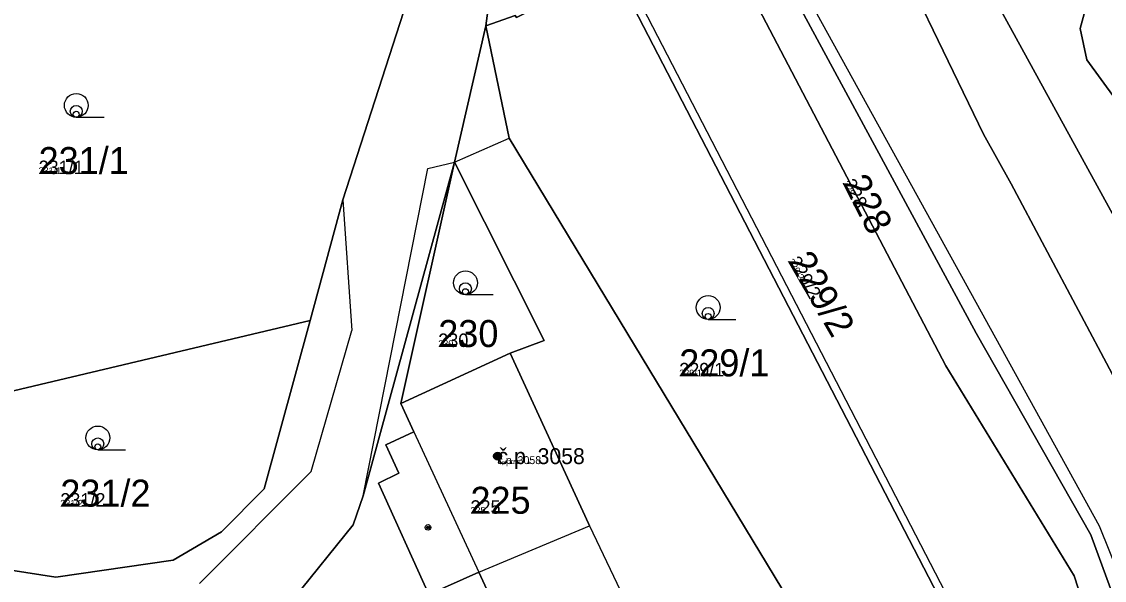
# Model space of a CAD drawing. Extents: x -759873 to -758487, y -975024 to -973516.
# Drawn here: x -759341.1 to -759272.8, y -974549.7 to -974514.5 of the extents above; entities that cross this region are included whole.
import ezdxf

# ---------------------------------------------------------------- set-up
doc = ezdxf.new("R2010")
doc.units = 0
for name, color, linetype in [('KAT_02_hranice parcel', 7, 'Continuous'), ('KAT_03_1000_st čísla parcelní', 7, 'Continuous'), ('KAT_03_1000_čísla parcelní', 7, 'Continuous'), ('KAT_03_1000_čísla popisná', 7, 'Continuous'), ('KAT_03_250_st čísla parcelní', 7, 'Continuous'), ('KAT_03_250_čísla parcelní', 7, 'Continuous'), ('KAT_03_250_čísla popisná', 7, 'Continuous'), ('KAT_03_500_st čísla parcelní', 7, 'Continuous'), ('KAT_03_500_čísla parcelní', 7, 'Continuous'), ('KAT_03_500_čísla popisná', 7, 'Continuous'), ('KAT_04_vnitřní kresba', 7, 'Continuous'), ('KAT_05_1000_značky kultur', 7, 'Continuous'), ('KAT_05_250_značky kultur', 7, 'Continuous'), ('KAT_05_500_značky kultur', 7, 'Continuous'), ('KAT_07_1000_značky budov', 7, 'Continuous'), ('KAT_07_250_značky budov', 7, 'Continuous'), ('KAT_07_500_značky budov', 7, 'Continuous'), ('KAT_14_plocha_budovy', 7, 'Continuous'), ('KAT_14_plocha_pozemek', 7, 'Continuous')]:
    doc.layers.add(name, color=color, linetype=linetype)

msp = doc.modelspace()

# ---------------------------------------------------------------- linework, layer by layer
at = {"layer": 'KAT_02_hranice parcel'}
for p, q in [((-759313.84, -974523.31), (-759311.87, -974514.72)), ((-759317.23, -974538.53), (-759313.84, -974523.31)), ((-759348.95, -974539.45), (-759322.95, -974533.3))]:
    msp.add_line(p, q, dxfattribs=at)
for points in [[(-759219.91, -974557.23), (-759223.23, -974544.52), (-759227.46, -974511.48), (-759228.38, -974500), (-759228.8, -974494.72), (-759282.45, -974508.14), (-759262.36, -974544.72), (-759253.18, -974586.18)], [(-759311.87, -974514.72), (-759311.45, -974511.72), (-759310.87, -974510.87), (-759307.53, -974503.56)], [(-759258.04, -974584.15), (-759260.14, -974570.39), (-759263.44, -974559.14), (-759268.52, -974545.49), (-759272.2, -974537), (-759272.35, -974536.66), (-759278.72, -974524.68), (-759280.47, -974521.55), (-759287.48, -974507.08)], [(-759296.72, -974509.67), (-759294.73, -974508.6), (-759280.94, -974534.1), (-759273.69, -974546.8), (-759272.46, -974550.18)], [(-759296.72, -974509.67), (-759282.85, -974536.15), (-759274.75, -974549.39), (-759274.26, -974550.88)], [(-759256.77, -974540.42), (-759273.95, -974516.88), (-759274.37, -974514.9), (-759273.84, -974512.95), (-759271.16, -974509.41)], [(-759303.45, -974511.79), (-759308.95, -974513.71), (-759309.93, -974514.21), (-759310.02, -974514.07), (-759311.87, -974514.72)], [(-759283.48, -974554.45), (-759282.94, -974552.16), (-759283.02, -974551.25), (-759303.45, -974511.79)], [(-759316.83, -974513.15), (-759320.88, -974525.7), (-759322.95, -974533.3)], [(-759293.18, -974550.19), (-759310.39, -974521.81), (-759311.87, -974514.72)], [(-759357.85, -974552.36), (-759338.42, -974554.93), (-759330.76, -974554.41), (-759323.99, -974550.85), (-759320.23, -974546.18), (-759319.6, -974544.34), (-759313.84, -974523.31)], [(-759313.84, -974523.31), (-759308.18, -974534.55), (-759310.32, -974535.35), (-759317.23, -974538.53)], [(-759322.95, -974533.3), (-759325.85, -974543.91), (-759328.53, -974546.61), (-759331.59, -974548.41), (-759338.98, -974549.47), (-759346.97, -974548.23)], [(-759304.47, -974566.09), (-759309.3, -974555.67), (-759312.31, -974549.16), (-759315.45, -974550.56), (-759318.62, -974543.56), (-759317.34, -974542.93), (-759318.17, -974541.13), (-759316.41, -974540.31), (-759317.23, -974538.53)]]:
    msp.add_lwpolyline(points, dxfattribs=at)
at = {"layer": 'KAT_03_1000_čísla popisná'}
msp.add_circle((-759311.12, -974541.85), 0.25, dxfattribs=at)
at = {"layer": 'KAT_03_250_čísla popisná'}
msp.add_circle((-759311.12, -974541.85), 0.0625, dxfattribs=at)
at = {"layer": 'KAT_03_500_čísla popisná'}
msp.add_circle((-759311.12, -974541.85), 0.125, dxfattribs=at)
at = {"layer": 'KAT_04_vnitřní kresba'}
for p, q in [((-759293.89, -974508.69), (-759273.17, -974546.25)), ((-759303.01, -974511.56), (-759282.58, -974551.02)), ((-759313.84, -974523.31), (-759310.39, -974521.81)), ((-759315.52, -974523.72), (-759313.84, -974523.31)), ((-759319.6, -974544.34), (-759315.52, -974523.72)), ((-759320.88, -974525.7), (-759320.32, -974533.93)), ((-759322.88, -974542.82), (-759320.32, -974533.93)), ((-759310.32, -974535.35), (-759305.38, -974546.1)), ((-759316.41, -974540.31), (-759312.31, -974549.16)), ((-759329.93, -974549.88), (-759322.88, -974542.82)), ((-759305.38, -974546.1), (-759305.32, -974546.24)), ((-759312.31, -974549.16), (-759305.32, -974546.24)), ((-759305.32, -974546.24), (-759302.34, -974552.5)), ((-759273.17, -974546.25), (-759268.31, -974558.38))]:
    msp.add_line(p, q, dxfattribs=at)
at = {"layer": 'KAT_05_1000_značky kultur'}
for p, q in [((-759337.693, -974520.49), (-759335.943, -974520.49)), ((-759313.143, -974531.67), (-759311.393, -974531.67)), ((-759297.833, -974533.23), (-759296.083, -974533.23)), ((-759336.333, -974541.45), (-759334.583, -974541.45))]:
    msp.add_line(p, q, dxfattribs=at)
for centre in [(-759337.693, -974519.74), (-759313.143, -974530.92), (-759297.833, -974532.48), (-759336.333, -974540.7)]:
    msp.add_circle(centre, 0.75, dxfattribs=at)
at = {"layer": 'KAT_05_250_značky kultur'}
for p, q in [((-759337.698, -974520.49), (-759337.261, -974520.49)), ((-759313.148, -974531.67), (-759312.711, -974531.67)), ((-759297.838, -974533.23), (-759297.401, -974533.23)), ((-759336.338, -974541.45), (-759335.901, -974541.45))]:
    msp.add_line(p, q, dxfattribs=at)
for centre in [(-759337.698, -974520.302), (-759313.148, -974531.482), (-759297.838, -974533.042), (-759336.338, -974541.262)]:
    msp.add_circle(centre, 0.187, dxfattribs=at)
at = {"layer": 'KAT_05_500_značky kultur'}
for p, q in [((-759337.696, -974520.49), (-759336.821, -974520.49)), ((-759313.147, -974531.67), (-759312.272, -974531.67)), ((-759297.836, -974533.23), (-759296.961, -974533.23)), ((-759336.336, -974541.45), (-759335.461, -974541.45))]:
    msp.add_line(p, q, dxfattribs=at)
for centre in [(-759337.696, -974520.115), (-759313.146, -974531.295), (-759297.836, -974532.855), (-759336.336, -974541.075)]:
    msp.add_circle(centre, 0.375, dxfattribs=at)
at = {"layer": 'KAT_07_1000_značky budov'}
for centre in [(-759311.127, -974541.849), (-759315.507, -974546.339)]:
    msp.add_circle(centre, 0.175, dxfattribs=at)
at = {"layer": 'KAT_07_250_značky budov'}
for centre in [(-759311.122, -974541.85), (-759315.502, -974546.34)]:
    msp.add_circle(centre, 0.0437, dxfattribs=at)
at = {"layer": 'KAT_07_500_značky budov'}
for centre in [(-759311.123, -974541.85), (-759315.503, -974546.34)]:
    msp.add_circle(centre, 0.0875, dxfattribs=at)
at = {"layer": 'KAT_14_plocha_budovy'}
msp.add_lwpolyline([(-759317.23, -974538.53), (-759316.41, -974540.31), (-759312.31, -974549.16), (-759305.32, -974546.24), (-759305.38, -974546.1), (-759310.32, -974535.35)], close=True, dxfattribs=at)
at = {"layer": 'KAT_14_plocha_pozemek'}
for points in [[(-759304.32, -974472.23), (-759304.33, -974475.03), (-759303.76, -974480.34), (-759303.8, -974484.62), (-759303.06, -974493.58), (-759303.28, -974495.84), (-759303.34, -974496.42), (-759301.57, -974504.18), (-759298.09, -974510.4), (-759296.72, -974509.67), (-759294.73, -974508.6), (-759280.94, -974534.1), (-759273.69, -974546.8), (-759272.46, -974550.18), (-759269.34, -974558.76), (-759265.86, -974568.96), (-759262.14, -974589.28), (-759261.35, -974613.2), (-759266.15, -974631.32), (-759272.2, -974639.41), (-759281.65, -974658.4)], [(-759272.35, -974536.66), (-759278.72, -974524.68), (-759280.47, -974521.55), (-759287.48, -974507.08), (-759289.52, -974501.85), (-759290.62, -974498.8), (-759292.96, -974492.33), (-759295.36, -974491.46), (-759295.58, -974491.38), (-759296.66, -974487.69), (-759297.16, -974485.12), (-759297.82, -974481.79), (-759297.54, -974478.48), (-759297.23, -974474.7)], [(-759228.8, -974494.72), (-759282.45, -974508.14), (-759262.36, -974544.72)], [(-759271.16, -974509.41), (-759273.84, -974512.95), (-759274.37, -974514.9), (-759273.95, -974516.88), (-759256.77, -974540.42)], [(-759256.77, -974540.42), (-759273.95, -974516.88), (-759274.37, -974514.9), (-759273.84, -974512.95), (-759271.16, -974509.41)], [(-759323.99, -974550.85), (-759320.23, -974546.18), (-759319.6, -974544.34), (-759313.84, -974523.31), (-759311.87, -974514.72), (-759311.45, -974511.72)], [(-759316.83, -974513.15), (-759320.88, -974525.7), (-759322.95, -974533.3), (-759325.85, -974543.91), (-759328.53, -974546.61), (-759331.59, -974548.41), (-759338.98, -974549.47), (-759346.97, -974548.23)]]:
    msp.add_lwpolyline(points, dxfattribs=at)
for points in [[(-759219.91, -974557.23), (-759227.79, -974493.47), (-759254.2, -974500.54), (-759275.54, -974505.92), (-759287.48, -974507.08), (-759280.47, -974521.55), (-759278.72, -974524.68), (-759272.35, -974536.66), (-759272.2, -974537), (-759268.52, -974545.49), (-759263.44, -974559.14), (-759260.14, -974570.39), (-759258.04, -974584.15), (-759256.76, -974585.37), (-759255.85, -974585.97), (-759255.42, -974586.26), (-759253.18, -974586.18), (-759262.36, -974544.72), (-759282.45, -974508.14), (-759228.8, -974494.72), (-759228.38, -974500), (-759227.46, -974511.48), (-759223.23, -974544.52)], [(-759322.95, -974533.3), (-759320.88, -974525.7), (-759316.83, -974513.15), (-759321.92, -974510.71), (-759324.16, -974509.55), (-759324.82, -974511.05), (-759329.47, -974509.2), (-759325.96, -974501.3), (-759338.54, -974498.57), (-759340.97, -974501.58), (-759344.1, -974504.48), (-759357.95, -974512.98), (-759350.06, -974534.56), (-759348.95, -974539.45)], [(-759303.01, -974511.56), (-759303.39, -974510.82), (-759307.06, -974503.74), (-759307.53, -974503.56), (-759310.87, -974510.87), (-759311.45, -974511.72), (-759311.87, -974514.72), (-759310.02, -974514.07), (-759309.93, -974514.21), (-759308.95, -974513.71), (-759303.45, -974511.79)], [(-759274.26, -974550.88), (-759272.46, -974550.18), (-759273.69, -974546.8), (-759280.94, -974534.1), (-759294.73, -974508.6), (-759296.72, -974509.67), (-759282.85, -974536.15), (-759274.75, -974549.39)], [(-759298.09, -974510.4), (-759303.01, -974511.56), (-759303.45, -974511.79), (-759283.02, -974551.25), (-759282.94, -974552.16), (-759283.48, -974554.45), (-759282.92, -974554.23), (-759278.36, -974552.47), (-759274.26, -974550.88), (-759274.75, -974549.39), (-759282.85, -974536.15), (-759296.72, -974509.67)], [(-759310.02, -974514.07), (-759311.87, -974514.72), (-759310.39, -974521.81), (-759293.18, -974550.19), (-759289.47, -974556.76), (-759283.48, -974554.45), (-759282.94, -974552.16), (-759283.02, -974551.25), (-759303.45, -974511.79), (-759308.95, -974513.71), (-759309.93, -974514.21)], [(-759310.39, -974521.81), (-759311.87, -974514.72), (-759313.84, -974523.31), (-759308.18, -974534.55), (-759310.32, -974535.35), (-759317.23, -974538.53), (-759316.41, -974540.31), (-759318.17, -974541.13), (-759317.34, -974542.93), (-759318.62, -974543.56), (-759315.45, -974550.56), (-759312.31, -974549.16), (-759309.3, -974555.67), (-759304.47, -974566.09), (-759292.58, -974563.69), (-759288.81, -974562.93), (-759289.47, -974556.76), (-759292.76, -974558.9), (-759296.66, -974552.54), (-759293.18, -974550.19)], [(-759317.34, -974542.93), (-759318.17, -974541.13), (-759316.41, -974540.31), (-759317.23, -974538.53), (-759313.84, -974523.31), (-759319.6, -974544.34), (-759320.23, -974546.18), (-759323.99, -974550.85), (-759330.76, -974554.41), (-759338.42, -974554.93), (-759357.85, -974552.36), (-759353.67, -974578.05), (-759311.94, -974568.97), (-759309.79, -974568.5), (-759304.47, -974566.09), (-759309.3, -974555.67), (-759312.31, -974549.16), (-759315.45, -974550.56), (-759318.62, -974543.56)], [(-759313.84, -974523.31), (-759317.23, -974538.53), (-759310.32, -974535.35), (-759308.18, -974534.55)], [(-759348.95, -974539.45), (-759346.97, -974548.23), (-759338.98, -974549.47), (-759331.59, -974548.41), (-759328.53, -974546.61), (-759325.85, -974543.91), (-759322.95, -974533.3)]]:
    msp.add_lwpolyline(points, close=True, dxfattribs=at)

# ---------------------------------------------------------------- texts
at = {"layer": 'KAT_03_1000_st čísla parcelní'}
msp.add_text('225', height=1.7, dxfattribs=at).set_placement((-759312.83, -974545.48))
at = {"layer": 'KAT_03_1000_čísla parcelní'}
for s, p in [('231/1', (-759340.07, -974524.07)), ('230', (-759314.86, -974534.97)), ('229/1', (-759299.66, -974536.82)), ('231/2', (-759338.7, -974545.03))]:
    msp.add_text(s, height=1.7, dxfattribs=at).set_placement(p)
for s, rotation, p in [('228', 297, (-759289.367, -974524.635)), ('229/2', 300, (-759292.826, -974529.555))]:
    msp.add_text(s, height=1.7, rotation=rotation, dxfattribs=at).set_placement(p)
at = {"layer": 'KAT_03_1000_čísla popisná'}
msp.add_text('č.p. 3058', height=1, dxfattribs=at).set_placement((-759311.12, -974542.35))
at = {"layer": 'KAT_03_250_st čísla parcelní'}
msp.add_text('225', height=0.425, dxfattribs=at).set_placement((-759312.83, -974545.48))
at = {"layer": 'KAT_03_250_čísla parcelní'}
for s, p in [('231/1', (-759340.07, -974524.07)), ('230', (-759314.86, -974534.97)), ('229/1', (-759299.66, -974536.82)), ('231/2', (-759338.7, -974545.03))]:
    msp.add_text(s, height=0.425, dxfattribs=at).set_placement(p)
for s, rotation, p in [('228', 297, (-759289.367, -974524.635)), ('229/2', 300, (-759292.826, -974529.555))]:
    msp.add_text(s, height=0.425, rotation=rotation, dxfattribs=at).set_placement(p)
at = {"layer": 'KAT_03_250_čísla popisná'}
msp.add_text('č.p. 3058', height=0.25, dxfattribs=at).set_placement((-759311.12, -974542.35))
at = {"layer": 'KAT_03_500_st čísla parcelní'}
msp.add_text('225', height=0.85, dxfattribs=at).set_placement((-759312.83, -974545.48))
at = {"layer": 'KAT_03_500_čísla parcelní'}
for s, p in [('231/1', (-759340.07, -974524.07)), ('230', (-759314.86, -974534.97)), ('229/1', (-759299.66, -974536.82)), ('231/2', (-759338.7, -974545.03))]:
    msp.add_text(s, height=0.85, dxfattribs=at).set_placement(p)
for s, rotation, p in [('228', 297, (-759289.367, -974524.635)), ('229/2', 300, (-759292.826, -974529.555))]:
    msp.add_text(s, height=0.85, rotation=rotation, dxfattribs=at).set_placement(p)
at = {"layer": 'KAT_03_500_čísla popisná'}
msp.add_text('č.p. 3058', height=0.5, dxfattribs=at).set_placement((-759311.12, -974542.35))

doc.saveas('drawing.dxf')
